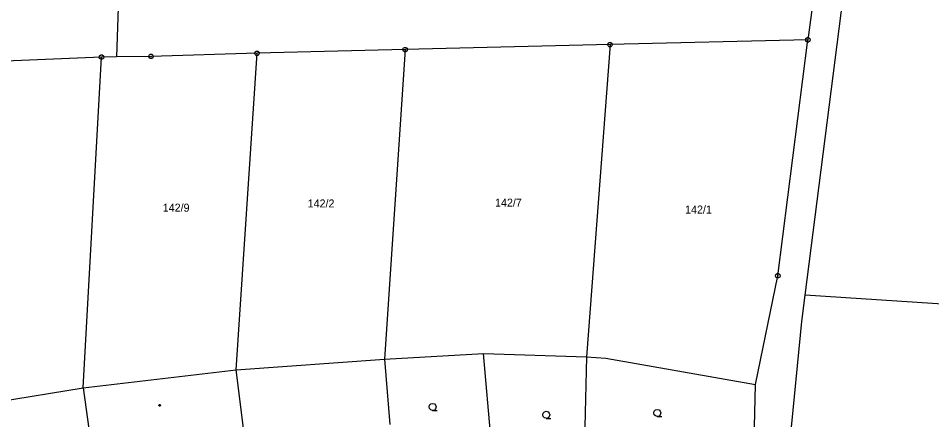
# Model space of a CAD drawing. Extents: x -812394 to -807601, y -1013098 to -1009266.
# Drawn here: x -809612.2 to -809418.3, y -1010671.6 to -1010586.4 of the extents above; entities that cross this region are included whole.
import ezdxf

# ---------------------------------------------------------------- set-up
doc = ezdxf.new("R2010")
doc.units = 0
for name, color, linetype in [('KN_HRANICE', 7, 'Continuous'), ('KN_KULTURY', 7, 'Continuous'), ('KN_MEZNIKY', 7, 'Continuous'), ('KN_PARCELY', 7, 'Continuous')]:
    doc.layers.add(name, color=color, linetype=linetype)

# ---------------------------------------------------------------- blocks, each defined once
blk = doc.blocks.new('304')
blk.add_lwpolyline([(0, 0), (-0.38, 0.1), (-0.65, 0.37), (-0.75, 0.74), (-0.65, 1.11), (-0.38, 1.38), (-0.01, 1.48), (0.36, 1.38), (0.63, 1.11), (0.73, 0.73), (0.63, 0.35), (0.36, 0.08), (-0.02, -0.02), (0.98, -0.02)])
blk = doc.blocks.new('402')
blk.add_lwpolyline([(0.09, 0.15), (0.18, 0), (0.09, -0.15), (-0.09, -0.15), (-0.18, 0), (-0.09, 0.15), (0.09, 0.15)])
blk = doc.blocks.new('105')
blk.add_line((-0.12, 0), (0.12, 0))
blk.add_lwpolyline([(0.15, 0.48), (0.4, 0.3), (0.5, 0.01), (0.4, -0.28), (0.15, -0.46), (-0.16, -0.46), (-0.41, -0.28), (-0.51, 0.01), (-0.41, 0.3), (-0.16, 0.48), (0.15, 0.48)])

msp = doc.modelspace()

# ---------------------------------------------------------------- linework, layer by layer
at = {"layer": 'KN_HRANICE'}
for p, q in [((-809588.81, -1010513.56), (-809591.38, -1010594.61)), ((-809445.19, -1010645.2), (-809431.77, -1010540.21)), ((-809440.59, -1010560.03), (-809444.6, -1010590.99)), ((-809486.59, -1010592), (-809530.09, -1010593.05)), ((-809486.59, -1010592), (-809491.57, -1010658.3)), ((-809444.6, -1010590.99), (-809486.59, -1010592)), ((-809450.97, -1010641.06), (-809444.6, -1010590.99)), ((-809594.54, -1010594.65), (-809642.04, -1010596.56)), ((-809598.46, -1010664.88), (-809594.54, -1010594.65)), ((-809591.38, -1010594.61), (-809594.54, -1010594.65)), ((-809584.05, -1010594.51), (-809591.38, -1010594.61)), ((-809561.54, -1010593.83), (-809584.05, -1010594.51)), ((-809565.97, -1010661.03), (-809561.54, -1010593.83)), ((-809530.09, -1010593.05), (-809561.54, -1010593.83)), ((-809530.09, -1010593.05), (-809534.45, -1010658.78)), ((-809455.72, -1010664.14), (-809450.97, -1010641.06)), ((-809445.9, -1010650.77), (-809445.19, -1010645.2)), ((-809388.09, -1010648.93), (-809445.19, -1010645.2)), ((-809448.82, -1010680.59), (-809445.9, -1010650.77)), ((-809534.45, -1010658.78), (-809513.45, -1010657.55)), ((-809513.45, -1010657.55), (-809491.57, -1010658.3)), ((-809511.21, -1010683.19), (-809513.45, -1010657.55)), ((-809491.57, -1010658.3), (-809492.27, -1010687)), ((-809491.57, -1010658.3), (-809487.51, -1010658.54)), ((-809487.51, -1010658.54), (-809455.72, -1010664.14)), ((-809565.97, -1010661.03), (-809534.45, -1010658.78)), ((-809534.45, -1010658.78), (-809533.33, -1010672.61)), ((-809598.46, -1010664.88), (-809565.97, -1010661.03)), ((-809564.36, -1010674), (-809565.97, -1010661.03)), ((-809456.08, -1010681.32), (-809455.72, -1010664.14)), ((-809633.83, -1010670.62), (-809598.46, -1010664.88)), ((-809598.46, -1010664.88), (-809596.67, -1010677.83))]:
    msp.add_line(p, q, dxfattribs=at)

# ---------------------------------------------------------------- block references
at = {"layer": 'KN_KULTURY'}
for name, p in [('402', (-809582.2, -1010668.57)), ('304', (-809524.25, -1010669.64)), ('304', (-809500.12, -1010671.31)), ('304', (-809476.55, -1010670.92))]:
    msp.add_blockref(name, p, dxfattribs=at)
at = {"layer": 'KN_MEZNIKY'}
for p in [(-809444.6, -1010590.99), (-809530.09, -1010593.05), (-809486.59, -1010592), (-809594.54, -1010594.65), (-809584.05, -1010594.51), (-809561.54, -1010593.83), (-809450.97, -1010641.06)]:
    msp.add_blockref('105', p, dxfattribs=at)

# ---------------------------------------------------------------- texts
at = {"layer": 'KN_PARCELY'}
for s, p in [('142/9', (-809581.56, -1010627.46)), ('142/2', (-809550.79, -1010626.56)), ('142/7', (-809511.01, -1010626.39)), ('142/1', (-809470.66, -1010627.85))]:
    msp.add_text(s, height=1.7, dxfattribs=at).set_placement(p)

doc.saveas('drawing.dxf')
